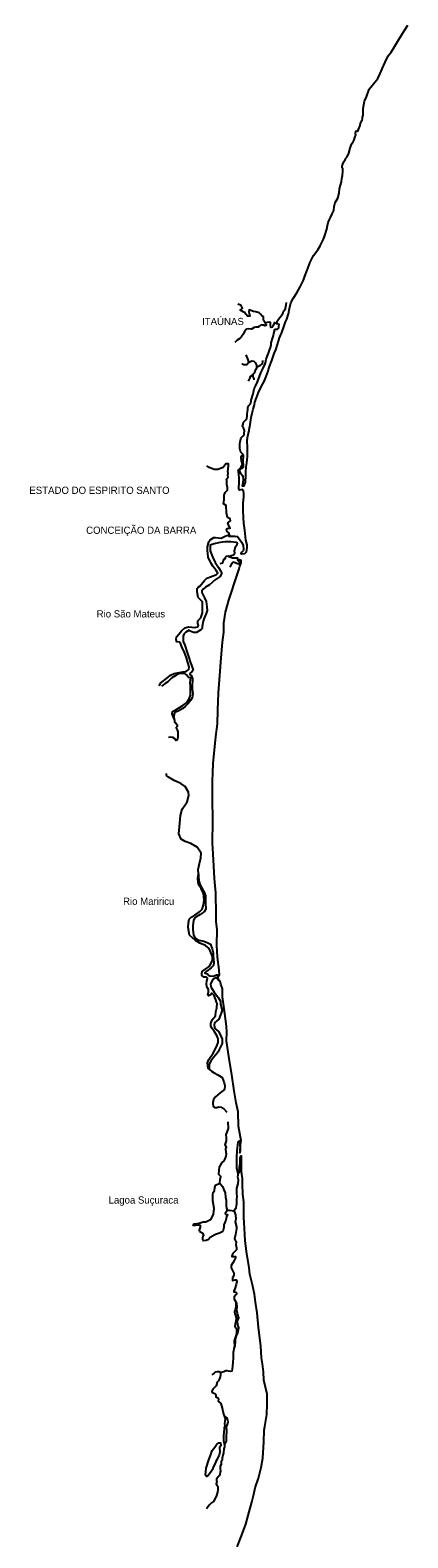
# Model space of a CAD drawing. Extents: x 662444 to 1640468, y 7452018 to 9606170.
# Drawn here: x 1037501 to 1071595, y 7846194 to 7982275 of the extents above; entities that cross this region are included whole.
import ezdxf

# ---------------------------------------------------------------- set-up
doc = ezdxf.new("R2010")
doc.units = 0
doc.layers.add('Level 1', color=7, linetype='Continuous')
doc.layers.add('Level 3', color=7, linetype='Continuous')

msp = doc.modelspace()

# ---------------------------------------------------------------- linework, layer by layer
at = {"layer": 'Level 1'}
for points in [[(1067512, 7974323), (1067514, 7974384), (1067515, 7974415), (1067551, 7974600), (1067560, 7974893), (1067561, 7975194), (1067689, 7975862), (1067871, 7976258), (1068107, 7976939), (1068380, 7977286), (1068884, 7977919), (1069105, 7978360), (1069264, 7978773), (1069536, 7979382), (1069824, 7979945), (1070096, 7980277), (1070427, 7980815), (1070688, 7981271), (1071125, 7981960), (1071595, 7982711)], [(1057121, 7943723), (1057133, 7943958), (1057111, 7944648), (1057084, 7945163), (1057107, 7945511), (1057196, 7945901), (1057266, 7946177), (1057302, 7946369), (1057321, 7946462), (1057417, 7947115), (1057445, 7947300), (1057527, 7947714), (1057622, 7948075), (1057749, 7948472), (1057787, 7948703), (1057929, 7949077), (1058128, 7949558), (1058385, 7950145), (1058628, 7950562), (1058803, 7951012), (1058987, 7951509), (1059023, 7951655), (1059092, 7951923), (1059309, 7952464), (1059527, 7953076), (1059691, 7953419), (1059821, 7953917), (1060024, 7954506), (1060223, 7954993), (1060392, 7955491), (1060552, 7955949), (1060675, 7956192), (1060813, 7956683), (1060912, 7957151), (1061035, 7957672), (1061247, 7958052), (1061570, 7958567), (1061886, 7959114), (1062174, 7959700), (1062284, 7960076), (1062509, 7960601), (1062601, 7960853), (1062792, 7961334), (1063087, 7961928), (1063472, 7962441), (1063691, 7962821), (1063971, 7963415), (1064096, 7963743), (1064283, 7964325), (1064348, 7964654), (1064417, 7964900), (1064492, 7965121), (1064623, 7965373), (1064763, 7965685), (1064920, 7966012), (1064945, 7966344), (1065026, 7966728), (1065276, 7967099), (1065406, 7967574), (1065433, 7967966), (1065512, 7968296), (1065591, 7968595), (1065645, 7968871), (1065685, 7969156), (1065720, 7969549), (1065723, 7969657), (1065726, 7969758), (1065675, 7969852), (1065669, 7969914), (1065680, 7970037), (1065714, 7970159), (1065718, 7970283), (1065773, 7970304), (1065839, 7970457), (1065942, 7970532), (1065977, 7970685), (1066105, 7970835), (1066254, 7971178), (1066383, 7971630), (1066509, 7971974), (1066687, 7972247), (1066745, 7972376), (1066812, 7972575), (1066854, 7972690), (1066879, 7972750), (1066903, 7972796), (1066905, 7972843), (1066874, 7972844), (1066877, 7972951), (1066879, 7972998), (1066913, 7973120), (1066914, 7973151), (1066952, 7973150), (1067046, 7973155), (1067142, 7973307), (1067293, 7973680), (1067336, 7973872), (1067428, 7974085), (1067459, 7974108), (1067512, 7974315), (1067512, 7974323)], [(1056718, 7943959), (1056699, 7944018), (1056644, 7944061), (1056548, 7944147), (1056499, 7944261), (1056456, 7944394), (1056421, 7944513), (1056417, 7944589), (1056421, 7944713), (1056436, 7944928), (1056465, 7945113), (1056527, 7945396), (1056592, 7945510), (1056640, 7945579), (1056726, 7945645), (1056815, 7945781), (1056819, 7945906), (1056840, 7946083), (1056842, 7946152), (1056771, 7946378), (1056675, 7946504), (1056771, 7946896), (1056985, 7947098), (1057058, 7947211), (1057088, 7947435), (1057102, 7947642), (1057144, 7948020), (1057165, 7948205), (1057255, 7948388), (1057390, 7948545), (1057452, 7948798), (1057462, 7948875), (1057640, 7949442), (1057723, 7949903), (1057864, 7950214), (1058019, 7950519), (1058313, 7951360), (1058493, 7951694), (1058665, 7952052), (1058697, 7952082), (1058756, 7952249), (1058804, 7952565), (1058881, 7952834), (1059005, 7953115), (1059087, 7953298), (1059113, 7953390), (1059190, 7953619), (1059249, 7953834), (1059271, 7954042), (1059410, 7954547), (1059460, 7954700), (1059512, 7954900), (1059549, 7955107), (1059560, 7955215), (1059646, 7955274), (1059770, 7955278), (1059840, 7955276), (1059936, 7955404), (1059939, 7955527), (1059975, 7955704), (1059777, 7955772), (1059581, 7955894), (1059524, 7955810), (1059409, 7955575), (1059375, 7955460), (1059221, 7955442), (1059189, 7955667), (1059196, 7955898), (1059074, 7955933), (1058726, 7955866), (1058584, 7956025), (1058565, 7956156), (1058565, 7956404), (1058436, 7956462), (1058295, 7956652), (1058183, 7956763), (1057885, 7956865), (1057671, 7956887), (1057276, 7957046), (1057241, 7956907), (1057239, 7956846), (1057265, 7956683), (1057302, 7956628), (1057320, 7956473), (1057112, 7956455), (1056979, 7956653), (1056913, 7956756), (1056738, 7956853), (1056587, 7956927), (1056496, 7956984), (1056484, 7957063), (1056560, 7957067), (1056671, 7957173), (1056548, 7957423), (1056441, 7957473), (1056259, 7957548)], [(1059777, 7955772), (1059812, 7955910), (1059824, 7956056), (1060047, 7956327), (1060048, 7956335), (1060153, 7956479), (1060313, 7956699), (1060332, 7956790), (1060358, 7956921), (1060556, 7957108), (1060566, 7957177), (1060605, 7957469), (1060635, 7957685)], [(1058726, 7955866), (1058752, 7955742), (1058797, 7955694), (1058803, 7955616), (1058686, 7955597), (1058574, 7955654), (1058489, 7955657), (1058358, 7955685), (1058169, 7955543), (1058106, 7955475), (1058060, 7955477), (1057875, 7955482), (1057719, 7955425), (1057469, 7955294), (1057255, 7955323), (1057023, 7955300), (1056863, 7955080), (1056757, 7954852), (1056562, 7954557), (1056421, 7954445), (1056177, 7954290), (1056106, 7954216), (1055987, 7954096)], [(1057202, 7952266), (1057257, 7952295), (1057243, 7952350), (1057171, 7952522), (1057150, 7952600), (1057008, 7952983)], [(1056622, 7952153), (1056645, 7952144), (1056789, 7952109), (1056942, 7952089), (1057050, 7952086), (1057202, 7952266), (1057437, 7952406), (1057499, 7952427), (1057707, 7952413), (1057826, 7952271), (1057839, 7952208), (1057919, 7952052), (1057924, 7951958), (1057919, 7951804), (1057884, 7951658), (1057811, 7951560), (1057719, 7951324), (1057616, 7951180), (1057536, 7951097), (1057379, 7951002), (1057323, 7950935), (1057304, 7950788), (1057240, 7950712), (1057190, 7950583)], [(1057616, 7951180), (1057613, 7951095), (1057610, 7950995), (1057652, 7950878), (1057696, 7950791), (1057702, 7950713)], [(1057924, 7951958), (1058062, 7951931), (1058295, 7952047), (1058461, 7952158), (1058505, 7952373), (1058507, 7952451)], [(1049133, 7923090), (1049310, 7923363), (1049917, 7923834), (1050167, 7924049), (1050510, 7924206), (1051298, 7924360), (1051521, 7924387), (1051651, 7924461), (1051834, 7924578), (1051862, 7924811), (1051696, 7925304), (1051600, 7925629), (1051405, 7926202), (1051213, 7926530), (1051106, 7926844), (1050995, 7927025), (1050742, 7927066), (1050674, 7927279), (1050723, 7927511), (1050932, 7927760), (1051163, 7928064), (1051467, 7928333), (1051788, 7928424), (1052094, 7928393), (1052326, 7928364), (1052625, 7928433), (1052702, 7928530), (1052643, 7928710), (1052651, 7928976), (1052695, 7929031), (1052913, 7929235), (1053053, 7929676), (1053055, 7930109), (1053063, 7930386), (1053062, 7930687), (1052681, 7931075), (1052569, 7931579), (1052566, 7931868), (1052655, 7931987), (1052827, 7932082), (1053245, 7932603), (1053441, 7932798), (1053774, 7932943), (1054031, 7933036), (1054331, 7933149), (1054440, 7933268), (1054288, 7933506), (1054003, 7933903), (1053800, 7934209), (1053582, 7934705), (1053515, 7935329), (1053524, 7935629), (1053644, 7936092), (1053755, 7936266), (1054068, 7936490), (1054238, 7936485), (1054480, 7936445), (1054745, 7936426), (1055099, 7936594), (1055260, 7936656), (1055485, 7936738), (1055428, 7936617), (1055990, 7936601), (1056221, 7936561), (1056455, 7936231), (1056608, 7936027), (1056738, 7935756), (1056760, 7935434), (1056724, 7935279), (1056604, 7935171), (1056527, 7935052), (1056578, 7934994), (1056876, 7935030), (1057029, 7935192), (1057103, 7935557), (1057079, 7935813), (1056965, 7936250), (1056895, 7937141), (1056798, 7937788), (1056770, 7938278), (1056724, 7938879), (1056732, 7939157), (1056734, 7939579), (1056783, 7940167), (1056791, 7940455), (1056766, 7940667), (1056643, 7940815), (1056397, 7940745), (1056338, 7940902), (1056355, 7941479), (1056367, 7941868), (1056344, 7942168), (1056299, 7942447), (1056292, 7942570), (1056554, 7942840), (1056667, 7943092), (1056571, 7943406), (1056546, 7943663), (1056549, 7943740)], [(1055485, 7936738), (1055447, 7936894), (1055282, 7937033), (1055211, 7937157), (1055290, 7937310), (1055544, 7937314), (1055434, 7937539), (1055358, 7937819), (1055574, 7937980), (1055548, 7938158), (1055329, 7938276), (1055215, 7938724), (1055181, 7939380), (1054941, 7939509), (1054989, 7939697), (1055006, 7939907), (1055006, 7940296), (1055099, 7940549), (1055327, 7940765), (1055313, 7940987), (1055247, 7941278), (1055262, 7941422), (1055269, 7941655), (1055240, 7941756), (1055361, 7941897), (1055334, 7942076), (1055372, 7942297), (1055333, 7942398), (1055392, 7942963), (1055397, 7943129), (1055174, 7943136), (1054910, 7942810), (1054449, 7942613), (1054110, 7942634), (1053670, 7942802), (1053451, 7942942)], [(1056718, 7943735), (1056691, 7943536), (1056685, 7943314), (1056730, 7943068), (1056734, 7942824), (1056679, 7942747), (1056474, 7942642), (1056375, 7942512), (1056495, 7942286), (1056689, 7942036), (1056721, 7941680), (1056667, 7941270), (1056653, 7941148), (1056822, 7941143), (1056949, 7941484), (1056965, 7942050), (1056973, 7942317), (1056975, 7942383), (1057011, 7942871), (1057053, 7943237), (1057094, 7943546), (1057121, 7943723)], [(1056549, 7943740), (1056565, 7943813), (1056591, 7943861), (1056632, 7943914), (1056662, 7943940), (1056680, 7943952), (1056718, 7943959), (1056735, 7943930), (1056730, 7943865), (1056718, 7943735)], [(1055427, 7930817), (1055753, 7931807), (1055868, 7932115), (1056252, 7933282), (1056369, 7933645), (1056419, 7933910), (1056534, 7934207), (1056539, 7934396), (1056371, 7934456), (1056243, 7934427), (1056249, 7934604), (1056132, 7934608), (1055773, 7934629), (1055521, 7934714), (1055386, 7934796), (1055566, 7934824), (1055844, 7934905), (1055987, 7935056), (1055961, 7935268), (1056047, 7935666), (1056190, 7935839), (1056226, 7935983), (1056090, 7936042), (1055624, 7936078), (1055117, 7936104), (1054840, 7936068), (1054489, 7936011), (1054222, 7935930), (1054115, 7935900), (1053761, 7935777), (1053745, 7935589), (1053737, 7935289), (1053953, 7934727), (1054204, 7934231), (1054508, 7933766), (1054721, 7933438), (1054780, 7933292), (1054779, 7933247), (1054665, 7932973), (1054210, 7932653), (1053689, 7932201), (1053333, 7931990), (1053127, 7931829), (1052984, 7931655), (1053001, 7931522), (1053252, 7931036), (1053380, 7930699), (1053440, 7930231), (1053483, 7929896), (1053380, 7929610), (1053209, 7929204), (1053127, 7928940), (1053017, 7928443), (1053033, 7928265), (1052902, 7928136), (1052504, 7927914), (1052250, 7927921), (1051936, 7928042), (1051843, 7928133), (1051562, 7927930), (1051387, 7927769), (1051308, 7927582), (1051315, 7927093), (1051475, 7926766), (1051688, 7926105), (1051834, 7925656), (1051989, 7925173), (1052057, 7924960), (1052203, 7924523), (1052082, 7924371), (1051941, 7924242), (1051916, 7924131), (1052041, 7924072), (1052158, 7923724), (1052126, 7922992), (1052120, 7922792), (1052172, 7922379), (1052119, 7922014), (1051974, 7921774), (1051754, 7921503), (1051622, 7921340), (1051492, 7921233), (1051275, 7921039), (1050877, 7920817), (1050630, 7920724), (1050499, 7920573), (1050459, 7920307), (1050486, 7920129), (1050477, 7920173), (1050329, 7920567), (1050347, 7920788), (1050744, 7920977), (1051272, 7921306), (1051641, 7921595), (1051862, 7921911), (1051978, 7922263), (1051990, 7922673), (1051970, 7923074), (1051947, 7923364), (1051986, 7923640), (1051991, 7923807)], [(1055386, 7934796), (1055183, 7934769), (1055107, 7934682), (1055103, 7934560), (1054974, 7934486), (1054906, 7934332), (1054869, 7934167), (1054623, 7934096)], [(1056243, 7934427), (1056439, 7934232), (1056382, 7934078), (1056129, 7934130), (1056015, 7934211), (1055825, 7934250), (1055649, 7934033), (1055526, 7933814)], [(1058595, 7854824), (1058619, 7855923), (1058671, 7856244), (1058852, 7857338), (1058892, 7858304), (1058898, 7859160), (1058609, 7860413), (1058569, 7861181), (1058464, 7861896), (1058396, 7862431), (1058334, 7863500), (1058112, 7865218), (1057982, 7866500), (1057854, 7867471), (1057749, 7868185), (1057574, 7869035), (1057318, 7869988), (1057272, 7870556), (1057022, 7872053), (1056904, 7873034), (1056853, 7874125), (1056788, 7875127), (1056787, 7875782), (1056777, 7876494), (1056704, 7877230), (1056656, 7878087), (1056662, 7878642), (1056610, 7879010), (1056565, 7879279), (1056568, 7879356), (1056580, 7879778), (1056569, 7880456), (1056575, 7880634), (1056511, 7880636), (1056433, 7880494), (1056420, 7880050), (1056375, 7879629), (1056365, 7879296), (1056361, 7879174), (1056275, 7879110), (1056172, 7879546), (1056155, 7880024), (1056158, 7880480), (1056199, 7881145), (1056257, 7881644), (1056276, 7881932), (1056363, 7882029), (1056435, 7881961), (1056419, 7881761), (1056445, 7881227), (1056436, 7880949), (1056460, 7881026), (1056501, 7881681), (1056534, 7882069), (1056489, 7882348), (1056319, 7883364), (1056273, 7884655), (1056097, 7885471), (1055908, 7886544), (1055698, 7887995), (1055467, 7889457), (1055229, 7891042), (1055253, 7891842), (1055217, 7892387), (1055000, 7893983), (1054852, 7895021), (1054852, 7895743), (1054717, 7896169), (1054661, 7896427), (1054506, 7896542), (1054439, 7896789), (1054562, 7896985), (1054583, 7896985), (1054576, 7897474), (1054409, 7898601), (1054357, 7899703), (1054388, 7901091), (1054303, 7901782), (1054281, 7902483), (1054254, 7904406), (1054145, 7905720), (1054072, 7906823), (1054021, 7907946), (1053964, 7908893), (1053991, 7910870), (1053970, 7912993), (1053963, 7914571), (1053992, 7915181), (1054030, 7916102), (1054150, 7917287), (1054271, 7918528), (1054410, 7919658), (1054447, 7920901), (1054514, 7922466), (1054613, 7924019), (1054745, 7925626), (1054871, 7927033), (1054972, 7927941), (1054996, 7928763), (1055142, 7929748), (1055427, 7930817)], [(1051991, 7923807), (1051791, 7923835), (1051608, 7924085), (1051474, 7924211), (1050933, 7924182), (1050653, 7924013), (1050298, 7923823), (1049927, 7923467), (1049679, 7923308), (1049365, 7923061)], [(1050486, 7920129), (1050534, 7919961), (1050529, 7919805), (1050643, 7919724), (1050766, 7919587), (1050762, 7919432), (1050694, 7919289), (1050774, 7919120), (1050832, 7918952), (1050823, 7918619), (1050819, 7918508), (1050813, 7918297), (1050746, 7918177), (1050640, 7918158), (1050528, 7918328), (1050373, 7918443), (1050204, 7918448), (1049991, 7918421)], [(1052687, 7906141), (1052666, 7906509), (1052789, 7907061), (1052910, 7907579), (1052943, 7908001), (1052578, 7908523), (1051996, 7908862), (1051504, 7909043), (1051140, 7909254), (1050932, 7909749), (1051013, 7910713), (1051076, 7911389), (1051230, 7911951), (1051551, 7912431), (1051662, 7912627), (1051827, 7913189), (1051794, 7913512), (1051491, 7914010), (1051097, 7914266), (1050492, 7914562), (1049992, 7914854), (1049817, 7915015), (1049801, 7915182)], [(1054506, 7896542), (1054373, 7896691), (1054248, 7896761), (1054193, 7896696), (1054000, 7896602), (1053777, 7896209), (1053800, 7895930), (1054124, 7895431), (1054511, 7894931), (1054682, 7894637), (1054674, 7894370), (1054836, 7893799), (1054548, 7892996), (1054343, 7892847), (1054137, 7892675), (1054120, 7892476), (1054174, 7892152), (1054515, 7891908), (1054644, 7891616), (1054843, 7891210), (1054831, 7890821), (1054572, 7890262), (1054470, 7890054), (1054272, 7889804), (1054043, 7889556), (1053822, 7889218), (1053666, 7888956), (1053653, 7888534), (1053580, 7888558), (1053510, 7889060), (1053626, 7889379), (1054023, 7889945), (1054336, 7890514), (1054464, 7890910), (1054484, 7891231), (1054366, 7891524), (1054154, 7891852), (1053931, 7892159), (1053811, 7892385), (1053818, 7892618), (1053944, 7892948), (1054219, 7893306), (1054251, 7893661), (1054357, 7894047), (1054379, 7894413), (1054319, 7894548), (1054251, 7894739), (1054126, 7895154), (1053930, 7895315), (1053846, 7895318), (1053789, 7895197), (1053586, 7895114), (1053546, 7895215), (1053607, 7895480), (1053603, 7895680), (1053462, 7895940), (1053427, 7896186), (1053446, 7896452), (1053496, 7896706), (1053414, 7896786), (1053213, 7896803), (1052985, 7896954), (1052989, 7897099), (1053028, 7897320), (1053147, 7897416), (1053665, 7897756), (1053809, 7897997), (1053957, 7898348), (1053966, 7898659), (1053671, 7899401), (1053330, 7899666), (1052829, 7899881), (1052424, 7900116), (1051878, 7900599), (1051761, 7901291), (1051784, 7901713), (1051857, 7902044), (1052021, 7902228), (1052354, 7902396), (1052808, 7902738), (1053026, 7902942), (1053084, 7903130), (1053143, 7903339), (1053208, 7903737), (1053152, 7904350), (1052943, 7904789), (1052751, 7905084), (1052664, 7905342), (1052632, 7905699), (1052687, 7906141), (1052698, 7905786), (1052770, 7905372), (1052847, 7905114), (1052967, 7904889), (1053239, 7904425), (1053315, 7904134), (1053344, 7903666), (1053344, 7903322), (1053347, 7903055), (1053364, 7902932), (1053198, 7902693)], [(1053198, 7902693), (1052853, 7902470), (1052498, 7902258), (1052346, 7902140), (1052234, 7901910), (1052178, 7901468), (1052177, 7901079), (1052248, 7900610), (1052378, 7900362), (1052533, 7900235), (1052721, 7900151), (1053172, 7900038), (1053549, 7899904), (1053788, 7899775), (1053935, 7899360), (1054019, 7898990), (1054010, 7898702), (1054088, 7898110), (1054038, 7897856), (1053841, 7897629), (1053700, 7897533), (1053580, 7897403), (1053365, 7897288), (1053257, 7897202), (1053255, 7897146), (1053497, 7897095), (1053589, 7896992), (1053735, 7896910), (1054030, 7896901), (1054308, 7897004), (1054414, 7897001), (1054411, 7896890), (1054439, 7896789), (1054506, 7896542)], [(1053580, 7888558), (1053879, 7888305), (1054107, 7888176), (1054451, 7887999), (1054606, 7887883), (1054844, 7887731), (1055020, 7887248), (1055075, 7886980), (1055045, 7886659), (1054645, 7886371), (1054232, 7885994), (1054066, 7885755), (1054005, 7885456), (1054027, 7885134), (1054140, 7885030), (1054340, 7885024), (1054522, 7885096), (1054733, 7885068), (1055023, 7884881), (1055258, 7884619)], [(1055909, 7875754), (1055886, 7875676), (1055486, 7875744), (1055381, 7875747), (1055275, 7875739), (1055098, 7875467), (1055138, 7875410), (1055306, 7875372), (1055226, 7875163), (1055175, 7874865), (1054993, 7874448), (1054975, 7874215), (1054901, 7873839), (1054590, 7873693), (1054238, 7873559), (1053744, 7873308), (1053601, 7873123), (1053387, 7873018), (1053133, 7873015), (1053095, 7873127), (1053080, 7873339), (1053180, 7873502), (1053090, 7873672), (1052819, 7873802), (1052782, 7873959), (1052875, 7874245), (1052869, 7874390), (1052711, 7874406), (1052435, 7874381), (1052224, 7874376), (1052292, 7874540), (1052759, 7874593), (1053132, 7874704), (1053364, 7874708), (1053847, 7874960), (1054051, 7875421), (1054097, 7875908), (1054002, 7876611), (1053988, 7877178), (1054025, 7877377), (1054136, 7877541), (1054176, 7877828), (1054236, 7878038), (1054632, 7878215), (1054662, 7878536), (1054724, 7878812), (1054539, 7878995), (1054551, 7879384), (1054601, 7879660), (1054846, 7880064), (1055010, 7880237), (1055109, 7880389), (1055191, 7880654), (1055238, 7880819), (1055201, 7880987), (1055158, 7881299), (1055216, 7881464), (1055106, 7881667), (1055212, 7882031), (1055231, 7882308), (1055197, 7882598), (1055277, 7882796), (1055393, 7883148), (1055390, 7883737)], [(1056275, 7879110), (1056223, 7878789), (1056279, 7878532), (1056246, 7878155), (1056128, 7877758), (1056134, 7877247), (1056148, 7877002), (1056141, 7876769), (1056116, 7876303), (1056112, 7876159), (1056075, 7875993), (1056029, 7875883), (1055909, 7875754), (1055957, 7875596), (1056045, 7875349), (1056064, 7874949), (1056015, 7874706), (1056118, 7874269), (1056134, 7874102), (1056033, 7873572), (1055958, 7873174), (1056086, 7872881), (1056080, 7872670), (1056123, 7872358), (1056118, 7872202), (1055900, 7871964), (1055791, 7871845), (1055724, 7871736), (1055709, 7871603), (1055826, 7871600), (1056026, 7871583), (1056033, 7871471), (1055920, 7871241), (1055787, 7871023), (1055653, 7870772), (1055646, 7870561), (1055796, 7870267), (1055896, 7870098), (1055890, 7869909), (1055845, 7869810), (1055767, 7869657), (1055762, 7869513), (1055770, 7869435), (1056015, 7869483), (1056099, 7869480), (1056168, 7869323), (1056086, 7869047), (1055969, 7868684), (1055888, 7868453), (1055887, 7868398), (1056055, 7868370), (1056116, 7868313), (1056123, 7868190), (1056079, 7868125), (1055915, 7867952), (1055919, 7867730), (1056060, 7867503), (1056074, 7867258), (1056067, 7867036), (1055996, 7866783), (1055937, 7866596), (1055964, 7866439), (1056044, 7866270), (1056090, 7866047), (1056059, 7865748), (1055999, 7865494), (1055971, 7865284), (1056052, 7865159), (1056123, 7865079), (1056132, 7864656), (1056061, 7864414), (1055931, 7863962), (1055926, 7863796), (1055953, 7863628), (1055903, 7863374), (1055836, 7862932), (1055833, 7862465), (1055787, 7862000), (1055768, 7861723), (1055738, 7861423), (1055711, 7861235), (1055573, 7861217), (1055405, 7861234), (1055300, 7861281), (1055174, 7861274), (1054991, 7861179), (1054853, 7861139), (1054694, 7861133), (1054569, 7861181), (1054379, 7861187), (1054209, 7861148), (1054102, 7861073), (1053907, 7860912)], [(1054632, 7878215), (1054743, 7878056), (1054865, 7877896), (1054993, 7877593), (1055091, 7877345), (1055143, 7876955), (1055198, 7876675), (1055200, 7876386), (1055193, 7876175), (1055218, 7875952), (1055275, 7875739)], [(1055903, 7863374), (1056013, 7863526), (1056034, 7863893), (1056042, 7864126), (1056135, 7864434), (1056249, 7864686), (1056326, 7865162), (1056260, 7865408), (1056208, 7865776), (1056333, 7866062), (1056217, 7866432), (1056153, 7866756), (1056184, 7867066), (1056151, 7867356), (1056060, 7867503)], [(1054694, 7861133), (1054678, 7860945), (1054651, 7860734), (1054569, 7860492), (1054513, 7860372), (1054393, 7860253), (1054298, 7859912), (1054168, 7859782), (1054005, 7859620), (1053913, 7859390), (1053974, 7859299), (1054235, 7859202), (1054251, 7859046), (1054258, 7858924), (1054435, 7858841), (1054494, 7858717), (1054478, 7858517), (1054714, 7858321), (1054771, 7858108), (1054884, 7857649), (1054969, 7857346), (1055007, 7857212), (1055094, 7856931), (1055088, 7856731), (1055049, 7856488), (1055064, 7856310), (1055027, 7856133), (1055023, 7856000), (1054995, 7855756), (1054961, 7855357), (1054950, 7854991), (1055005, 7854711), (1055054, 7854599), (1055049, 7854421), (1054979, 7854223), (1054958, 7853857), (1054909, 7853659), (1054838, 7853383), (1054822, 7853206), (1054754, 7853074), (1054747, 7852819), (1054668, 7852666), (1054651, 7852455), (1054686, 7852221), (1054652, 7852133), (1054614, 7851945), (1054567, 7851780), (1054459, 7851706), (1054337, 7851498), (1054312, 7851377), (1054361, 7851253), (1054303, 7851066), (1054362, 7850920), (1054443, 7850839), (1054434, 7850539), (1054406, 7850318), (1054278, 7849922), (1054065, 7849484), (1053870, 7849345), (1053663, 7849130), (1053411, 7848815)], [(1055054, 7854599), (1055176, 7854795), (1055212, 7854916), (1055218, 7855138), (1055224, 7855316), (1055239, 7855460), (1055267, 7855681), (1055241, 7855882), (1055240, 7856204), (1055345, 7856501), (1055361, 7856679), (1055297, 7857014), (1055007, 7857212)], [(1054022, 7852563), (1053973, 7852354), (1053786, 7852093), (1053577, 7851832), (1053405, 7851727), (1053315, 7851863), (1053376, 7852483), (1053631, 7853231), (1053780, 7853627), (1053920, 7854067), (1054161, 7854371), (1054339, 7854654), (1054521, 7854771), (1054680, 7854766), (1054724, 7854487), (1054582, 7854347), (1054623, 7853956), (1054551, 7853670), (1054427, 7853396), (1054348, 7853242), (1054269, 7853078), (1054155, 7852793), (1054022, 7852563)], [(1056195, 7845385), (1056574, 7846384), (1056965, 7847428), (1057284, 7848552), (1057511, 7849411), (1057692, 7850139), (1057825, 7850702), (1058126, 7851571), (1058367, 7852530), (1058498, 7853382), (1058525, 7853903), (1058595, 7854824)]]:
    msp.add_lwpolyline(points, dxfattribs=at)

# ---------------------------------------------------------------- texts
at = {"layer": 'Level 3'}
for s, height, p in [('ITAÚNAS', 650.7, (1053020, 7955656)), ('ESTADO DO ESPIRITO SANTO', 650.1, (1037429, 7940419)), ('CONCEIÇÃO DA BARRA', 650.02, (1042551, 7936815)), ('Rio São Mateus', 649.75, (1043503, 7929267)), ('Rio Mariricu', 648.88, (1045888, 7903327)), ('Lagoa Suçuraca', 647.93, (1044581, 7876366))]:
    msp.add_text(s, height=height, dxfattribs=at).set_placement(p)

doc.saveas('drawing.dxf')
